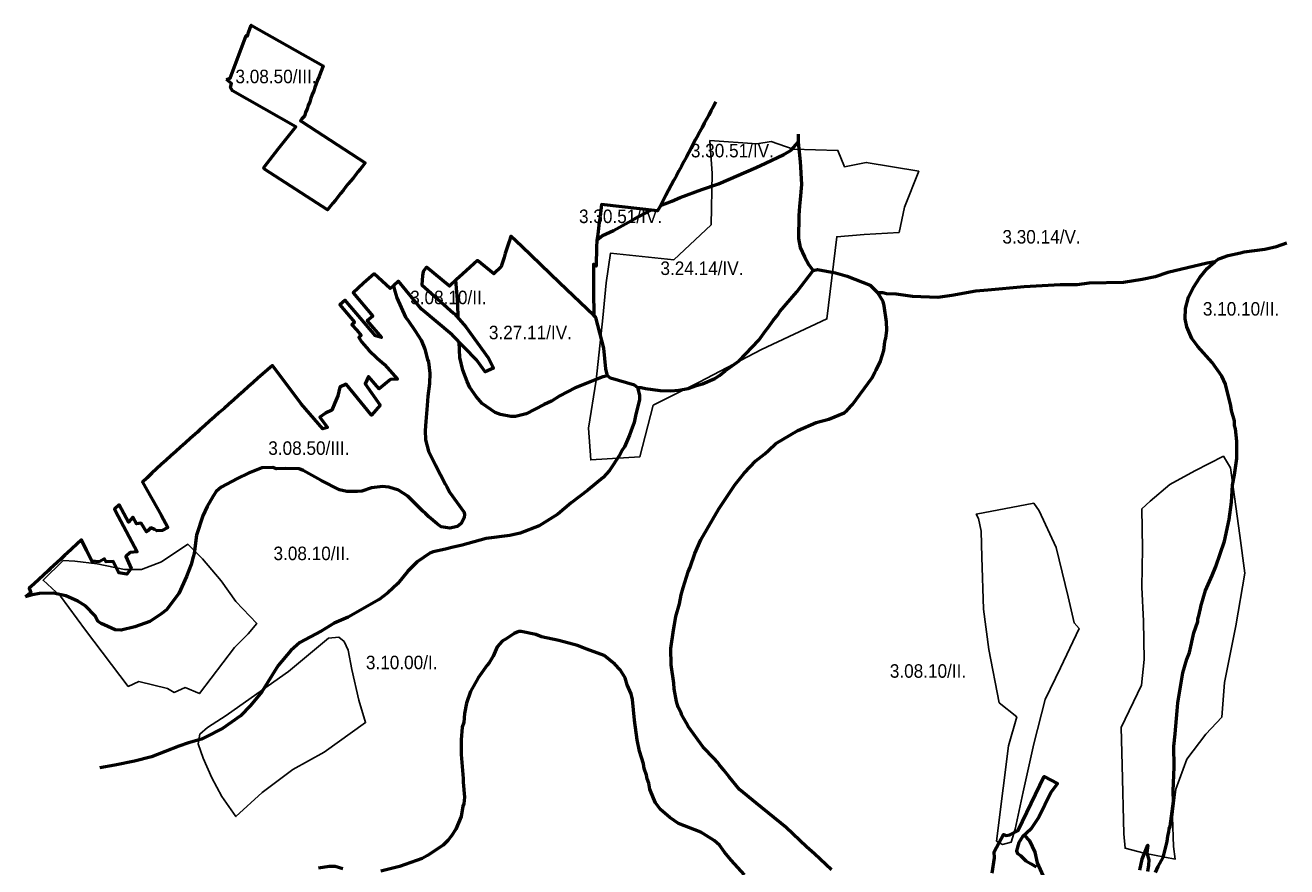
# Model space of a CAD drawing. Extents: x -555506 to -553028, y -1186750 to -1182668.
# Drawn here: x -555107 to -553240, y -1183913 to -1182668 of the extents above; entities that cross this region are included whole.
import ezdxf
from ezdxf.enums import TextEntityAlignment as Align

# ---------------------------------------------------------------- set-up
doc = ezdxf.new("R2010")
doc.units = 0
doc.header["$LTSCALE"] = 8
doc.layers.add('21', color=7, linetype='Continuous', lineweight=53)
doc.layers.add('41', color=7, linetype='Continuous', lineweight=25)
doc.layers.add('22', color=7, linetype='Continuous')

msp = doc.modelspace()

# ---------------------------------------------------------------- linework, layer by layer
at = {"layer": '21'}
msp.add_lwpolyline([(-554809.56, -1182748.02), (-554804.24, -1182746.09), (-554780.38, -1182683.03), (-554778.75, -1182683.79), (-554776.86, -1182678.36), (-554774.88, -1182673.03), (-554772.9, -1182667.71), (-554666.73, -1182727.7), (-554668.72, -1182733.01), (-554670.72, -1182738.37), (-554672.62, -1182743.74), (-554674.7, -1182749.11), (-554676.68, -1182754.39), (-554678.64, -1182759.62), (-554680.59, -1182764.96), (-554682.62, -1182770.33), (-554684.58, -1182775.61), (-554686.46, -1182780.94), (-554688.52, -1182786.3), (-554690.42, -1182791.52), (-554692.44, -1182796.71), (-554694.32, -1182802.05), (-554698.03, -1182806.37), (-554700.16, -1182809.13), (-554697.56, -1182810.81), (-554604.33, -1182871.18), (-554607.57, -1182875.37), (-554611.33, -1182880.08), (-554615.1, -1182884.8), (-554618.76, -1182889.39), (-554622.34, -1182893.87), (-554625.97, -1182898.29), (-554629.38, -1182902.63), (-554633.35, -1182907.44), (-554637.08, -1182912.33), (-554640.7, -1182916.69), (-554644.85, -1182921.99), (-554648.51, -1182926.36), (-554652.29, -1182931.05), (-554660.11, -1182940.98), (-554753.5, -1182880.52), (-554754.24, -1182878), (-554732.55, -1182850.06), (-554706.8, -1182817.93), (-554800.79, -1182765), (-554803.48, -1182759.79), (-554802.43, -1182753.89)], close=True, dxfattribs=at)
for points in [[(-554085.58, -1182781.01), (-554089.43, -1182788.23), (-554092.75, -1182794.46), (-554095.99, -1182800.56), (-554099.16, -1182806.51), (-554102.5, -1182812.78), (-554105.78, -1182818.94), (-554108.98, -1182824.94), (-554112.18, -1182830.94), (-554115.38, -1182836.94), (-554118.76, -1182843.3), (-554122.11, -1182849.59), (-554125.47, -1182855.88), (-554128.92, -1182862.36), (-554132.55, -1182869.18), (-554136.23, -1182876.09), (-554139.94, -1182883.05), (-554143.66, -1182890.03), (-554147.38, -1182897.03), (-554151.42, -1182904.61), (-554155.33, -1182911.94), (-554159.3, -1182919.39), (-554163.4, -1182927.1), (-554167.47, -1182934.74), (-554171.63, -1182942.54), (-554254.38, -1182933.03), (-554255.52, -1182941.75), (-554256.73, -1182950.69), (-554257.85, -1182959.52), (-554258.99, -1182968.54), (-554260.14, -1182977.6), (-554261.3, -1182986.71), (-554262.22, -1182995.89), (-554262.21, -1183005.1), (-554262.33, -1183014.59), (-554262.38, -1183024.08), (-554266.38, -1183021.27), (-554266.32, -1183061.49), (-554266.18, -1183097.12), (-554316.77, -1183048.71), (-554372.68, -1182995.2), (-554388.93, -1182979.65), (-554391.47, -1182987.64), (-554393.27, -1182993.57), (-554395.17, -1182999.46), (-554397, -1183005.38), (-554398.87, -1183011.31), (-554400.71, -1183017.23), (-554402.67, -1183023.1), (-554403.33, -1183025.09), (-554413.98, -1183035.48), (-554437.96, -1183015.71), (-554449.17, -1183025.95), (-554460.24, -1183035.89), (-554469.42, -1183044.22), (-554479.62, -1183053.63), (-554513.4, -1183025.76), (-554518.6, -1183032.04), (-554519.39, -1183038.52), (-554520.07, -1183045.01), (-554520.76, -1183051.66), (-554473.59, -1183093.62), (-554472.09, -1183094.95), (-554455.4, -1183113.91), (-554421.72, -1183160.34), (-554414.65, -1183175.07), (-554426.66, -1183180.83), (-554439.49, -1183162.97), (-554475.52, -1183125.71), (-554520.97, -1183088.05)], [(-553963.349, -1182828.897), (-553963.75, -1182830.5), (-553963.75, -1182834.768), (-553963.75, -1182837.487), (-553963.75, -1182838.575), (-553963.75, -1182840.625)], [(-554167.42, -1182934.646), (-554150.312, -1182928), (-554138.437, -1182922.876), (-554106.187, -1182911), (-554081.625, -1182902.5), (-554025.687, -1182878.376), (-554012.125, -1182872.001), (-553984.562, -1182859.25), (-553973.937, -1182852.501), (-553963.75, -1182840.625)], [(-553963.75, -1182840.625), (-553960.375, -1182869.501), (-553958.687, -1182903.376), (-553960.375, -1182925.501), (-553961.625, -1182935.626), (-553962.5, -1182949.125), (-553963.312, -1182983.125), (-553960.375, -1182996.626), (-553954.437, -1183010.251), (-553947.625, -1183022.125), (-553941.312, -1183030.625)], [(-554261.13, -1182985.33), (-554252.938, -1182978.878), (-554236.812, -1182971.626), (-554205.875, -1182954.251), (-554183.375, -1182942.375), (-554181.404, -1182941.417)], [(-553346.727, -1183017.836), (-553342.187, -1183014.001), (-553339.687, -1183012.75), (-553327.375, -1183008.5), (-553309.125, -1183004.75), (-553303.625, -1183003.001), (-553273.125, -1182999.251), (-553255.75, -1182995.375), (-553240.474, -1182989.514)], [(-554201.187, -1183203.626), (-554196.125, -1183203.626), (-554189.75, -1183205.251), (-554167.687, -1183208.251), (-554152.437, -1183208.625), (-554140.125, -1183207.75), (-554126.562, -1183205.251), (-554114.25, -1183201.001), (-554104.937, -1183198.5), (-554087.125, -1183190.376), (-554079.937, -1183186.25), (-554071.437, -1183179.376), (-554050.687, -1183164.125), (-554021.875, -1183133.626), (-554012.125, -1183120.001), (-554007.875, -1183115.001), (-554000.625, -1183104.75), (-553993.875, -1183096.251), (-553990.5, -1183091.251), (-553965.437, -1183062.375), (-553941.312, -1183030.625)], [(-553941.312, -1183030.625), (-553934.937, -1183029.376), (-553908.25, -1183034.001), (-553891.25, -1183039.125), (-553856.937, -1183052.25), (-553845.875, -1183063.625)], [(-553346.727, -1183017.836), (-553358.312, -1183019.625), (-553416.375, -1183033.5), (-553435.062, -1183039.875), (-553454.562, -1183044.126), (-553482.125, -1183048.376), (-553533, -1183049.626), (-553550.812, -1183051.751), (-553575.812, -1183051.751), (-553629.25, -1183054.751), (-553683.062, -1183059.875), (-553700.5, -1183061.126), (-553736.062, -1183067.501), (-553756.875, -1183070.501), (-553794.187, -1183069.126), (-553818.75, -1183065.75), (-553832.75, -1183065.376), (-553838.25, -1183063.625), (-553845.875, -1183063.625)], [(-553434.625, -1183921.375), (-553430.812, -1183912.875), (-553423.625, -1183899.376), (-553417.25, -1183875.626), (-553416.375, -1183867.126), (-553415.125, -1183862), (-553414.312, -1183856.875), (-553413, -1183853.501), (-553407.937, -1183816.251), (-553408.375, -1183801.001), (-553407.062, -1183765.376), (-553407.5, -1183734.751), (-553405.812, -1183716.125), (-553402.437, -1183682.251), (-553401.562, -1183670.375), (-553394.375, -1183626.251), (-553388.437, -1183605.875), (-553384.625, -1183595.75), (-553377.812, -1183566.876), (-553372.312, -1183550.001), (-553372.312, -1183546.626), (-553370.187, -1183539.75), (-553369.375, -1183534.75), (-553368.062, -1183531.25), (-553367.625, -1183527.876), (-553360.875, -1183504.125), (-553351.125, -1183482.126), (-553345.625, -1183468.501), (-553338.812, -1183449.876), (-553332.437, -1183431.251), (-553325.687, -1183399.001), (-553322.312, -1183373.626), (-553320.562, -1183348.126), (-553317.625, -1183332.876), (-553314.25, -1183309.126), (-553314.25, -1183283.75), (-553316.375, -1183265.001), (-553317.625, -1183260), (-553318.062, -1183253.125), (-553322.312, -1183237.875), (-553323.125, -1183231.126), (-553331.187, -1183198.876), (-553336.687, -1183187), (-553351.125, -1183166.626), (-553372.312, -1183143), (-553380.812, -1183131.126), (-553388.437, -1183114.126), (-553391, -1183102.25), (-553390.125, -1183087.001), (-553385.875, -1183070), (-553382.5, -1183063.251), (-553379.125, -1183056.5), (-553368.937, -1183041.25), (-553358.312, -1183027.625), (-553346.727, -1183017.836)], [(-554520.97, -1183088.05), (-554554.89, -1183046.35), (-554562.53, -1183053.13), (-554567.43, -1183057.47), (-554591.15, -1183035.39), (-554598.91, -1183042.47), (-554606.78, -1183049.62), (-554614.53, -1183056.65), (-554622.33, -1183063.77), (-554593.26, -1183098.14), (-554601.26, -1183104.98), (-554580.02, -1183129.98), (-554589.05, -1183127.49), (-554611.53, -1183101.05), (-554628.97, -1183080.53), (-554634.15, -1183074.43), (-554638.03, -1183077.94), (-554641.91, -1183081.47), (-554620.03, -1183107.23), (-554624, -1183110.83), (-554616.95, -1183119.13), (-554610.45, -1183126.73), (-554613.79, -1183129.59), (-554609.19, -1183136.97), (-554598.93, -1183148.57), (-554586.83, -1183160.5), (-554575.55, -1183169.73), (-554556.74, -1183191.61), (-554566.7, -1183192.05), (-554575.24, -1183198.88), (-554583.79, -1183205.7), (-554599.54, -1183187.59), (-554604.55, -1183198.21), (-554582.34, -1183229.95), (-554594.82, -1183244.98), (-554621.27, -1183212.77), (-554632.58, -1183199.03), (-554642.11, -1183203.45), (-554644.88, -1183216.26), (-554649.38, -1183226.72), (-554653.85, -1183237.43), (-554663.25, -1183241.85), (-554671.5, -1183247.6), (-554659.9, -1183262.96), (-554667.03, -1183264.88), (-554699.17, -1183227.83), (-554741.66, -1183171.12), (-554748.95, -1183177.43), (-554755.99, -1183183.75), (-554763.1, -1183190.08), (-554770.25, -1183196.43), (-554777.42, -1183202.78), (-554784.53, -1183209.17), (-554791.73, -1183215.56), (-554798.88, -1183221.86), (-554806.02, -1183228.28), (-554813.12, -1183234.65), (-554820.36, -1183241.01), (-554827.49, -1183247.43), (-554834.63, -1183253.83), (-554841.79, -1183260.25), (-554848.95, -1183266.59), (-554852.59, -1183269.75), (-554856.15, -1183272.92), (-554863.29, -1183279.39), (-554870.39, -1183285.71), (-554874.36, -1183289.36), (-554877.44, -1183292.2), (-554884.69, -1183298.58), (-554891.82, -1183304.91), (-554898.92, -1183311.49), (-554906.1, -1183317.74), (-554913.17, -1183324.08), (-554920.26, -1183330.57), (-554927.09, -1183337.26), (-554933.97, -1183343.87), (-554906.3, -1183392.96), (-554896.2, -1183410.77), (-554904.61, -1183415.44), (-554912.81, -1183415.84), (-554916.31, -1183414.13), (-554921.57, -1183411.56), (-554926.22, -1183415.89), (-554928.05, -1183417.59), (-554935.83, -1183404.66), (-554942.63, -1183405.5), (-554947.99, -1183395.55), (-554954.54, -1183403.27), (-554968.43, -1183377.25), (-554975.5, -1183383.63), (-554969.8, -1183394.42), (-554941.94, -1183447.21), (-554952.33, -1183447.96), (-554958.47, -1183453.8), (-554950.83, -1183471.64), (-554957.16, -1183480.2), (-554969.02, -1183477.84), (-554977.32, -1183461.31), (-554987.72, -1183461.68), (-554989.94, -1183457.2), (-554998.08, -1183461.92)], [(-554466.549, -1183101.202), (-554467.437, -1183079.751), (-554470.312, -1183045.043)], [(-554562.53, -1183053.13), (-554560.346, -1183061.339), (-554557.75, -1183070.875), (-554544.625, -1183099.751), (-554540.812, -1183104.75), (-554530.625, -1183120.001), (-554521.687, -1183133.626), (-554516.187, -1183147.126), (-554511.937, -1183162.5), (-554510.687, -1183165.876), (-554508.562, -1183182.75), (-554509, -1183198), (-554511.562, -1183216.751), (-554512.812, -1183230.25), (-554514.5, -1183254.001), (-554515.375, -1183267.626), (-554514.937, -1183281.125), (-554510.687, -1183298.125), (-554504.75, -1183310.001), (-554500.5, -1183318.501), (-554485.25, -1183347.251), (-554483.562, -1183350.751), (-554479.312, -1183359.125), (-554458.562, -1183388.001), (-554457.25, -1183391.375), (-554457.687, -1183396.5), (-554462.375, -1183405), (-554467.875, -1183409.626), (-554478.875, -1183412.125), (-554492.062, -1183410), (-554498, -1183405.376), (-554510.25, -1183395.251), (-554514.937, -1183390.126), (-554519.187, -1183386.751), (-554541.187, -1183364.626), (-554555.187, -1183355.75), (-554569.187, -1183351.501), (-554578.937, -1183350.251), (-554595.062, -1183352.376), (-554609.5, -1183357), (-554615.812, -1183357.876), (-554631.5, -1183357.5), (-554642.562, -1183355.375), (-554669.25, -1183341.376), (-554696, -1183326.501), (-554701.875, -1183324.376), (-554722.687, -1183323.5), (-554735.375, -1183324), (-554740.937, -1183322.251), (-554757.437, -1183322.751), (-554776.937, -1183330.375), (-554793.5, -1183338.375), (-554817.25, -1183351.125), (-554824.875, -1183357.876), (-554829.5, -1183364.626), (-554838.437, -1183380.001), (-554844.812, -1183393.5), (-554854.125, -1183422.376), (-554857.5, -1183449.5), (-554858.75, -1183454.626), (-554861.75, -1183465.626), (-554868.937, -1183483.376), (-554880, -1183508.875), (-554898.625, -1183532.625), (-554906.687, -1183539.376), (-554922.812, -1183550.001), (-554945.25, -1183558.001), (-554965.625, -1183563.126), (-554974.125, -1183562.25), (-554985.125, -1183557.625), (-554994.875, -1183552.875), (-554997.812, -1183550.876), (-555000, -1183549.501), (-555004.687, -1183541.251), (-555017.813, -1183527.626), (-555029.687, -1183520.001), (-555047.437, -1183512.001), (-555065.687, -1183508.125), (-555086.437, -1183508.625), (-555096.625, -1183510.75), (-555106.923, -1183513.357)], [(-554133.75, -1183500.375), (-554126.562, -1183476.625), (-554123.187, -1183469.876), (-554116.375, -1183449.5), (-554107.5, -1183429.126), (-554081.187, -1183383.375), (-554066.375, -1183361.25), (-554057.437, -1183347.75), (-554043.5, -1183330.751), (-554026.062, -1183312.126), (-554012.937, -1183301.875), (-554007.437, -1183296.876), (-553996.812, -1183286.625), (-553964.187, -1183267.626), (-553937.062, -1183255.75), (-553918.375, -1183250.626), (-553895.5, -1183241.251), (-553890.812, -1183237.501), (-553883.187, -1183229.001), (-553854.375, -1183190), (-553850.125, -1183181.501), (-553848, -1183178.126), (-553841.625, -1183164.625), (-553837, -1183149.25), (-553835.312, -1183135.751), (-553834, -1183130.626), (-553832.312, -1183118.75), (-553832.75, -1183106.875), (-553836.125, -1183083.125), (-553837.812, -1183076.375), (-553845.875, -1183063.625)], [(-554245.71, -1183186.601), (-554248.25, -1183176.001), (-554251.187, -1183145.5), (-554262.81, -1183100.35), (-554266.18, -1183097.12)], [(-554245.71, -1183186.601), (-554252.5, -1183188.251), (-554293.625, -1183204.375), (-554316.062, -1183216.251), (-554328.375, -1183223.876), (-554339.375, -1183229.001), (-554366.125, -1183242.626), (-554381.812, -1183246.876), (-554389, -1183246.876), (-554404.25, -1183243.876), (-554411.875, -1183240.875), (-554431.375, -1183227.25), (-554440.312, -1183217.125), (-554449.625, -1183203.626), (-554453.437, -1183195.126), (-554459.812, -1183178.126), (-554464.062, -1183159.501), (-554465.056, -1183136.531)], [(-554201.187, -1183203.626), (-554205.875, -1183200.125), (-554241.062, -1183190), (-554245.71, -1183186.601)], [(-554201.187, -1183203.626), (-554198.625, -1183215), (-554198.625, -1183221.751), (-554204.125, -1183245.501), (-554206.25, -1183255.75), (-554210.5, -1183267.626), (-554213.062, -1183274.375), (-554220.687, -1183291.376), (-554224.062, -1183296.376), (-554227.5, -1183303.25), (-554242.75, -1183326.501), (-554252.062, -1183337.126), (-554274.937, -1183355.75), (-554299.562, -1183374.375), (-554319.062, -1183391.375), (-554347.062, -1183408.375), (-554375, -1183419.375), (-554390.25, -1183422.751), (-554425.5, -1183427.375), (-554461.062, -1183437.126), (-554475.937, -1183440.625), (-554485.25, -1183443.125), (-554503.937, -1183446.876), (-554508.562, -1183449), (-554527.625, -1183461.75), (-554541.187, -1183475.375), (-554556.062, -1183494), (-554570.875, -1183507.5), (-554583.625, -1183517.75), (-554629.375, -1183543.626), (-554650.187, -1183552.501), (-554669.25, -1183564.375), (-554701.062, -1183581.375), (-554714.625, -1183593.251), (-554733.25, -1183615.25), (-554757.437, -1183654.251), (-554774, -1183674.625), (-554788.812, -1183689.876), (-554815.5, -1183708.5), (-554840.562, -1183721.25), (-554846.5, -1183724.25), (-554866, -1183729.75), (-554880.375, -1183734.751), (-554920.687, -1183750.126), (-554945.687, -1183756.876), (-554974.937, -1183762.751), (-554996.931, -1183766.455)], [(-554998.08, -1183461.92), (-555008.94, -1183460.95), (-555016.79, -1183444.75), (-555024.25, -1183429.37), (-555031.27, -1183435.88), (-555038.3, -1183442.38), (-555045.38, -1183448.95), (-555048.86, -1183452.17), (-555052.35, -1183455.43), (-555055.75, -1183458.74), (-555059.32, -1183461.97), (-555066.31, -1183468.45), (-555069.87, -1183471.69), (-555073.35, -1183474.96), (-555080.36, -1183481.47), (-555087.4, -1183487.96), (-555094.43, -1183494.49), (-555101.51, -1183500.99), (-555099.02, -1183506.99), (-555107.46, -1183513.79)], [(-553914.125, -1183917.501), (-553939.625, -1183893.751), (-553951.437, -1183883.626), (-553981.125, -1183854.75), (-554025.687, -1183819.126), (-554050.25, -1183798.876), (-554065.5, -1183780.125), (-554073.562, -1183770), (-554080.375, -1183761.5), (-554082.875, -1183758.126), (-554088, -1183753), (-554104.125, -1183736.125), (-554126.125, -1183705.5), (-554128.687, -1183700.5), (-554135.5, -1183688.626), (-554136.75, -1183685.25), (-554141, -1183676.75), (-554143.5, -1183668.25), (-554146.937, -1183649.625), (-554147.75, -1183641.126), (-554151.562, -1183614.001), (-554152, -1183590.251), (-554148.187, -1183563.126), (-554146.5, -1183554.626), (-554144.375, -1183542.75), (-554139.312, -1183524.125), (-554136.75, -1183510.5), (-554133.75, -1183500.375)], [(-554043.062, -1183925.125), (-554062.562, -1183903.126), (-554072.75, -1183891.25), (-554079.937, -1183881.125), (-554088, -1183874.25), (-554107.5, -1183861.625), (-554140.562, -1183849.251), (-554153.25, -1183840.375), (-554167.25, -1183828.501), (-554174.875, -1183818.376), (-554177.437, -1183811.501), (-554182.937, -1183798), (-554184.625, -1183789.5), (-554187.187, -1183782.75), (-554188.062, -1183777.626), (-554191.437, -1183767.501), (-554192.312, -1183760.625), (-554198.25, -1183742), (-554201.625, -1183725), (-554205.875, -1183696.25), (-554208.812, -1183665.751), (-554210.937, -1183657.25), (-554216.437, -1183643.626), (-554219.812, -1183633.501), (-554227.062, -1183621.625), (-554235.125, -1183613.125), (-554250.812, -1183600.376), (-554276.25, -1183591.126), (-554290.25, -1183585.625), (-554317.75, -1183578.001), (-554343.25, -1183572.875), (-554351.687, -1183569.501), (-554373.312, -1183564.751), (-554377.125, -1183564.751), (-554383.937, -1183567.75), (-554395.812, -1183575.876), (-554401.75, -1183579.25), (-554408.937, -1183587.75), (-554413.625, -1183597.875), (-554414.875, -1183601.251), (-554420.812, -1183611.376), (-554423.75, -1183614.875), (-554436.937, -1183633.501), (-554448.375, -1183653.875), (-554454.312, -1183670.751), (-554457.25, -1183686.001), (-554458.562, -1183699.625), (-554460.687, -1183706.375), (-554462.375, -1183725), (-554462.375, -1183747.125), (-554459.375, -1183782.25), (-554459.375, -1183787.751), (-554457.25, -1183809.876), (-554458.562, -1183820.001), (-554459.812, -1183823.376), (-554462.375, -1183838.75), (-554470.437, -1183857.375), (-554476.375, -1183867.5), (-554481.875, -1183874.25), (-554489.062, -1183881.125), (-554512.375, -1183896.376), (-554520, -1183900.625), (-554553.5, -1183912.875), (-554581.062, -1183919.626)], [(-553676.66, -1183922.68), (-553673.2, -1183899.7), (-553673.4, -1183890.9), (-553659.67, -1183865.22), (-553655.99, -1183866.78), (-553650.17, -1183865.76), (-553638.05, -1183859.17), (-553599.33, -1183779.63), (-553579.54, -1183789.62), (-553589.46, -1183803.27), (-553607.57, -1183839.44), (-553619.44, -1183857.32), (-553631.4, -1183868.6), (-553636.95, -1183877.35), (-553640.65, -1183889.28), (-553638.87, -1183893.41), (-553634.67, -1183896.58), (-553626.65, -1183904.05), (-553618.67, -1183908.59), (-553611.55, -1183913.18)], [(-553628.917, -1183866.258), (-553621.187, -1183874.75), (-553613.125, -1183891.626), (-553609.75, -1183907), (-553603.375, -1183921.375), (-553598.312, -1183932.376), (-553594.591, -1183937.571)], [(-553458.14, -1183917.89), (-553454.56, -1183901.72), (-553446.14, -1183881.07), (-553447.47, -1183892.13), (-553446.37, -1183896.02), (-553444.85, -1183902.91), (-553445.24, -1183910.57), (-553446.66, -1183920.16)], [(-554637.437, -1183915.876), (-554648.937, -1183912.875), (-554657.812, -1183912.5), (-554673.5, -1183915)]]:
    msp.add_lwpolyline(points, dxfattribs=at)
at = {"layer": '41'}
msp.add_line((-553451.559, -1183606.348), (-553455.604, -1183644.39), dxfattribs=at)
for points in [[(-554110.282, -1183196.136), (-554018.051, -1183147.572), (-553920.966, -1183102.245), (-553906.403, -1182980.833), (-553865.951, -1182977.596), (-553814.172, -1182974.358), (-553806.082, -1182937.125), (-553785.047, -1182883.704), (-553862.715, -1182870.754), (-553895.077, -1182877.229), (-553904.785, -1182852.947), (-553971.127, -1182851.328), (-554003.488, -1182839.996), (-554024.523, -1182843.234), (-554094.101, -1182838.377), (-554090.865, -1182886.942), (-554092.483, -1182963.026), (-554147.498, -1183014.829), (-554241.346, -1183005.116), (-554247.819, -1183048.824), (-554252.673, -1183100.626), (-554262.381, -1183192.899)], [(-554262.381, -1183192.899), (-554273.708, -1183264.127), (-554270.472, -1183311.072), (-554197.658, -1183306.216), (-554178.241, -1183230.131), (-554110.282, -1183196.136)], [(-553455.604, -1183644.39), (-553485.538, -1183706.715), (-553483.92, -1183762.564), (-553481.493, -1183864.549), (-553479.875, -1183885.594), (-553451.559, -1183892.879), (-553405.443, -1183901.782), (-553407.87, -1183883.166), (-553409.488, -1183839.458), (-553404.634, -1183798.178), (-553388.453, -1183753.901), (-553360.137, -1183716.668), (-553336.675, -1183691.576), (-553332.63, -1183640.584), (-553315.64, -1183556.405), (-553302.695, -1183478.702), (-553309.976, -1183422.853), (-553323.73, -1183322.486), (-553334.248, -1183305.488), (-553376.318, -1183327.342), (-553413.534, -1183347.578), (-553442.659, -1183371.86), (-553454.795, -1183383.192), (-553453.986, -1183442.038), (-553454.795, -1183499.506), (-553452.368, -1183549.689), (-553451.559, -1183606.348)], [(-553614.985, -1183375.017), (-553699.934, -1183391.205), (-553696.698, -1183397.681), (-553692.653, -1183416.297), (-553691.844, -1183454.988), (-553689.417, -1183531.882), (-553681.326, -1183591.778)], [(-553681.326, -1183591.778), (-553665.955, -1183670.291), (-553640.065, -1183691.336), (-553652.201, -1183734.234), (-553660.291, -1183796.559), (-553670, -1183875.072), (-553661.1, -1183879.928), (-553648.156, -1183876.69), (-553642.492, -1183857.265), (-553630.357, -1183802.225), (-553614.985, -1183731.157), (-553597.995, -1183665.595), (-553575.342, -1183618.649), (-553547.835, -1183560.372), (-553555.116, -1183552.278), (-553564.015, -1183513.426), (-553581.814, -1183440.579), (-553606.895, -1183386.349), (-553614.985, -1183375.017)], [(-554939.55, -1183638.881), (-554896.671, -1183649.404), (-554886.963, -1183655.07), (-554870.782, -1183647.785), (-554849.747, -1183656.688), (-554797.968, -1183588.698), (-554777.742, -1183568.463), (-554764.797, -1183553.084), (-554795.541, -1183520.708), (-554817.385, -1183489.95), (-554844.892, -1183457.574), (-554866.737, -1183435.72), (-554905.571, -1183461.621), (-554935.505, -1183472.953), (-554960.585, -1183472.953), (-555001.037, -1183464.858), (-555034.208, -1183460.811), (-555051.198, -1183460.002)], [(-555051.198, -1183460.002), (-555081.132, -1183489.141), (-555055.243, -1183512.614), (-555018.027, -1183562.797), (-554954.922, -1183646.166), (-554939.55, -1183638.881)], [(-554756.707, -1183803.191), (-554711.401, -1183769.196), (-554665.285, -1183743.295), (-554603.798, -1183699.587), (-554613.507, -1183666.401), (-554624.024, -1183621.074), (-554629.688, -1183592.745), (-554635.351, -1183579.795), (-554643.441, -1183573.319), (-554658.813, -1183574.938), (-554717.873, -1183624.312), (-554772.888, -1183663.164), (-554810.104, -1183689.065), (-554837.611, -1183706.872), (-554848.938, -1183716.585), (-554851.365, -1183731.154), (-554844.083, -1183752.199)], [(-554844.083, -1183752.199), (-554831.139, -1183781.337), (-554816.576, -1183808.857), (-554795.541, -1183838.805), (-554756.707, -1183803.191)]]:
    msp.add_lwpolyline(points, dxfattribs=at)

# ---------------------------------------------------------------- texts
at = {"layer": '22', "width": 0.95}
for s, p in [('3.08.50/III.', (-554736.315, -1182753.508)), ('3.30.51/IV.', (-554060.902, -1182863.228)), ('3.30.51/IV.', (-554226.412, -1182960.482)), ('3.30.14/V.', (-553603.378, -1182990.786)), ('3.24.14/IV.', (-554105.961, -1183037.314)), ('3.08.10/II.', (-554481.208, -1183080.517)), ('3.10.10/II.', (-553308.14, -1183097.45)), ('3.27.11/IV.', (-554359.838, -1183132.389)), ('3.08.50/III.', (-554687.735, -1183303.472)), ('3.08.10/II.', (-554683.527, -1183459.291)), ('3.10.00/I.', (-554550.304, -1183620.726)), ('3.08.10/II.', (-553771.429, -1183633.329))]:
    msp.add_text(s, height=20, dxfattribs=at).set_placement(p, align=Align.CENTER)

doc.saveas('drawing.dxf')
